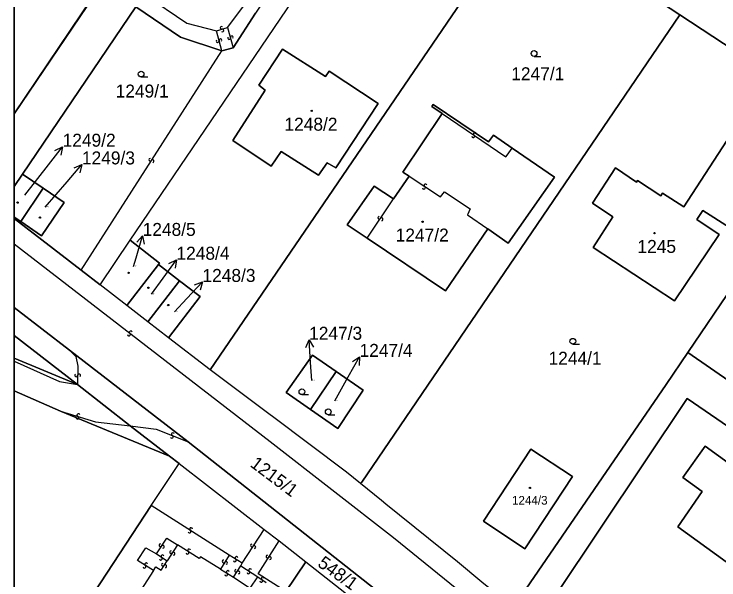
# Model space of a CAD drawing. Extents: x -600309 to -598967, y -1161267 to -1160292.
# Drawn here: x -600308.5 to -600216.2, y -1160403.9 to -1160329.8 of the extents above; entities that cross this region are included whole.
import ezdxf

# ---------------------------------------------------------------- set-up
doc = ezdxf.new("R2010")
doc.units = 0
for name, color, linetype in [('Level 1', 7, 'Continuous'), ('Level 13', 7, 'Continuous'), ('Level 3', 7, 'Continuous'), ('Level 4', 7, 'Continuous'), ('Level 5', 7, 'Continuous'), ('Level 57', 7, 'Continuous'), ('Level 60', 7, 'Continuous'), ('Vrstva 60', 7, 'Continuous'), ('Vrstva 63', 7, 'Continuous')]:
    doc.layers.add(name, color=color, linetype=linetype)

msp = doc.modelspace()

# ---------------------------------------------------------------- linework, layer by layer
at = {"layer": 'Level 1'}
for p, q in [((-600308.541, -1160342.846), (-600296.1, -1160324.42)), ((-600308.541, -1160352.373), (-600307.43, -1160350.76)), ((-600308.541, -1160356.385), (-600307.64, -1160356.98)), ((-600299.76, -1160363.36), (-600308.541, -1160356.593)), ((-600301.3, -1160373.82), (-600308.541, -1160368.236)), ((-600308.541, -1160371.919), (-600300.23, -1160378.34)), ((-600308.541, -1160374.894), (-600300.23, -1160378.34)), ((-600308.541, -1160379.184), (-600302.45, -1160381.81))]:
    msp.add_line(p, q, dxfattribs=at)
for points in [[(-600293.32, -1160359.44), (-600257.23, -1160306.23)], [(-600282.85, -1160376.42), (-600241.86, -1160316.33)], [(-600229.14, -1160324.7), (-600221.27, -1160329.87)], [(-600307.43, -1160350.76), (-600292.59, -1160328.82)], [(-600292.59, -1160328.82), (-600286.75, -1160332.8), (-600281.32, -1160334.59)], [(-600279.81, -1160334.2), (-600276.88, -1160329.68)], [(-600263.15, -1160391.32), (-600262.97, -1160391.13), (-600221.27, -1160329.87)], [(-600221.27, -1160329.87), (-600199.77, -1160343.98)], [(-600281.32, -1160334.59), (-600279.81, -1160334.2)], [(-600273.37, -1160334.39), (-600267.73, -1160337.96), (-600267.24, -1160337.25), (-600260.83, -1160341.49), (-600266.36, -1160349.95), (-600267.49, -1160349.28), (-600268.63, -1160350.88), (-600273.52, -1160347.79), (-600274.86, -1160349.72), (-600279.89, -1160346.36), (-600275.61, -1160339.77), (-600276.46, -1160339.11), (-600273.37, -1160334.39)], [(-600252.44, -1160342.8), (-600253.8, -1160341.89), (-600253.63, -1160341.64), (-600246.36, -1160346.54), (-600245.7, -1160345.67), (-600243.27, -1160347.35)], [(-600256.77, -1160351.05), (-600257.58, -1160350.49), (-600252.44, -1160342.8)], [(-600220.24, -1160374.15), (-600199.77, -1160343.98)], [(-600214.78, -1160357.78), (-600208.56, -1160348.24), (-600214.01, -1160344.68), (-600220.76, -1160355.06), (-600223.56, -1160353.24), (-600223.79, -1160353.59), (-600226.82, -1160351.62), (-600226.94, -1160351.8), (-600229.71, -1160349.95), (-600232.74, -1160354.59), (-600230.04, -1160356.36), (-600232.65, -1160360.4), (-600221.98, -1160367.38), (-600216.14, -1160358.66), (-600219.03, -1160356.71), (-600218.26, -1160355.51), (-600214.78, -1160357.78)], [(-600243.27, -1160347.35), (-600237.72, -1160351.15), (-600243.76, -1160359.82), (-600246.44, -1160357.95)], [(-600304.72, -1160352.6), (-600307.43, -1160350.76)], [(-600258.79, -1160354.01), (-600256.77, -1160351.05)], [(-600307.64, -1160356.98), (-600304.94, -1160358.83), (-600301.97, -1160354.48), (-600304.72, -1160352.6)], [(-600304.72, -1160352.6), (-600307.64, -1160356.98)], [(-600262.24, -1160359.16), (-600264.87, -1160357.4), (-600261.34, -1160352.32), (-600258.79, -1160354.01)], [(-600246.44, -1160357.95), (-600251.99, -1160366.04), (-600262.24, -1160359.16)], [(-600297.28, -1160365.27), (-600293.32, -1160359.44)], [(-600293.32, -1160359.44), (-600289.47, -1160362.42), (-600289.61, -1160362.6)], [(-600293.77, -1160367.98), (-600289.61, -1160362.6)], [(-600289.61, -1160362.6), (-600286.84, -1160364.74)], [(-600297.28, -1160365.27), (-600299.76, -1160363.36)], [(-600286.84, -1160364.74), (-600291, -1160370.12)], [(-600286.84, -1160364.74), (-600284.15, -1160366.82), (-600288.31, -1160372.2)], [(-600293.77, -1160367.98), (-600297.28, -1160365.27)], [(-600029.82, -1160579.77), (-600047.03, -1160569.17), (-600070.48, -1160554.56), (-600111.58, -1160529.03), (-600126.1, -1160520.21), (-600138.76, -1160511.76), (-600151.84, -1160502.25), (-600159.7, -1160496.34), (-600170.75, -1160487.14), (-600176.1, -1160482.15), (-600185.22, -1160473.25), (-600206.08, -1160453.49), (-600217.54, -1160442.6), (-600229.41, -1160431.52), (-600247.87, -1160415.66), (-600254.33, -1160410.63), (-600285.71, -1160385.84), (-600301.3, -1160373.82), (-600308.541, -1160368.236)], [(-600291, -1160370.12), (-600293.77, -1160367.98)], [(-600288.31, -1160372.2), (-600291, -1160370.12)], [(-600282.85, -1160376.42), (-600288.31, -1160372.2)], [(-600285.71, -1160385.84), (-600301.3, -1160373.82)], [(-600266.32, -1160376.62), (-600269.42, -1160374.51), (-600272.89, -1160379.38), (-600269.71, -1160381.61)], [(-600243.16, -1160407.61), (-600242.98, -1160407.4), (-600223.07, -1160378.32), (-600220.24, -1160374.15)], [(-600220.24, -1160374.15), (-600205.39, -1160384.4)], [(-600263.15, -1160391.32), (-600264.98, -1160389.81), (-600274.67, -1160382.53), (-600274.96, -1160382.3), (-600282.85, -1160376.42)], [(-600266.32, -1160376.62), (-600269.71, -1160381.61)], [(-600266.32, -1160376.62), (-600262.78, -1160379.08), (-600266.12, -1160384.1), (-600269.71, -1160381.61)], [(-600293.32, -1160383.74), (-600300.23, -1160378.34)], [(-600235.83, -1160413.97), (-600237.42, -1160405.71), (-600220.3, -1160380.18), (-600204.05, -1160391.32), (-600193.72, -1160398.49)], [(-600302.45, -1160381.81), (-600288.16, -1160387.74)], [(-600288.16, -1160387.74), (-600293.32, -1160383.74)], [(-600000.45, -1160595.4), (-600016.14, -1160587.57), (-600029.82, -1160579.77), (-600047.03, -1160569.17), (-600070.48, -1160554.56), (-600111.58, -1160529.03), (-600126.1, -1160520.21), (-600138.76, -1160511.76), (-600151.84, -1160502.25), (-600159.7, -1160496.34), (-600170.75, -1160487.14), (-600176.1, -1160482.15), (-600185.22, -1160473.25), (-600206.08, -1160453.49), (-600217.54, -1160442.6), (-600229.41, -1160431.52), (-600247.87, -1160415.66), (-600254.33, -1160410.63), (-600285.71, -1160385.84)], [(-600241.6, -1160399.85), (-600247.03, -1160396.26), (-600240.79, -1160386.82), (-600235.36, -1160390.41), (-600241.6, -1160399.85)], [(-600212.69, -1160403.4), (-600221.56, -1160396.97), (-600218.35, -1160392.37), (-600220.87, -1160390.5), (-600217.96, -1160386.41), (-600206.49, -1160394.71), (-600212.69, -1160403.4)], [(-600288.16, -1160387.74), (-600286.91, -1160388.7)], [(-600290.57, -1160394.2), (-600286.91, -1160388.7)], [(-600286.91, -1160388.7), (-600275.76, -1160397.32)], [(-600243.16, -1160407.61), (-600244.73, -1160406.23), (-600247.25, -1160404.22), (-600250.43, -1160401.59), (-600259.8, -1160394.03), (-600260.37, -1160393.54), (-600263.15, -1160391.32)], [(-600290.57, -1160394.2), (-600298.04, -1160405.59)], [(-600275.76, -1160397.32), (-600273.8, -1160398.84)], [(-600273.8, -1160398.84), (-600270.28, -1160401.56)], [(-600272.94, -1160405.48), (-600270.28, -1160401.56)], [(-600270.28, -1160401.56), (-600257.21, -1160411.88)]]:
    msp.add_lwpolyline(points, dxfattribs=at)
at = {"layer": 'Level 13'}
for centre, start, end in [((-600281.336, -1160331.592), 52.49674, 284.59474), ((-600281.243, -1160331.948), 232.28229, 104.87229), ((-600281.858, -1160333.327), 142.53529, 14.63329), ((-600281.502, -1160333.233), 322.32084, 194.91084), ((-600280.357, -1160332.929), 142.87323, 15.46323), ((-600280.002, -1160332.832), 323.08768, 195.18568), ((-600248.155, -1160345.489), 3.10076, 235.19876), ((-600248.364, -1160345.792), 182.88631, 55.47631), ((-600290.694, -1160348.879), 94.71508, 326.81308), ((-600290.385, -1160349.08), 274.50062, 147.09062), ((-600254.811, -1160352.554), 184.0808, 56.6708), ((-600254.608, -1160352.246), 4.29526, 236.39326), ((-600260.672, -1160356.476), 93.55449, 325.65249), ((-600260.368, -1160356.683), 273.34003, 145.93003), ((-600293.257, -1160371.495), 359.4942, 232.0842), ((-600293.484, -1160371.785), 179.70865, 51.80665), ((-600300.394, -1160377.135), 125.96479, 358.55479), ((-600300.026, -1160377.146), 306.17924, 178.27724), ((-600300.114, -1160382.344), 20.19058, 252.28857), ((-600300.225, -1160382.696), 199.97612, 72.56612), ((-600287.868, -1160385.191), 195.66402, 68.25402), ((-600287.731, -1160384.849), 15.87847, 247.97647), ((-600285.351, -1160397.295), 4.7523, 237.3423), ((-600285.55, -1160397.605), 184.96676, 57.06475), ((-600289.353, -1160399.397), 93.87472, 325.97271), ((-600289.047, -1160399.602), 273.66026, 146.25026), ((-600285.61, -1160400.075), 4.60827, 237.19828), ((-600277.363, -1160399.438), 94.22204, 326.32004), ((-600277.056, -1160399.641), 274.00759, 146.59759), ((-600289.086, -1160400.848), 3.58765, 235.68564), ((-600287.954, -1160400.3), 94.40946, 326.99946), ((-600287.646, -1160400.501), 274.62391, 146.72191), ((-600285.811, -1160400.385), 184.82273, 56.92073), ((-600279.401, -1160401.075), 4.75373, 237.34373), ((-600275.325, -1160400.889), 94.80658, 326.90458), ((-600275.015, -1160401.09), 274.59213, 147.18213), ((-600291.242, -1160401.904), 5.07903, 237.66903), ((-600289.293, -1160401.153), 183.37319, 55.96319), ((-600289.034, -1160401.959), 94.56577, 326.66376), ((-600281.065, -1160401.51), 94.64636, 327.23636), ((-600280.755, -1160401.711), 274.86082, 146.95882), ((-600279.6, -1160401.385), 184.96819, 57.06619), ((-600291.439, -1160402.215), 185.29348, 57.39148), ((-600288.726, -1160402.16), 274.35131, 146.94131), ((-600280.53, -1160402.905), 5.24774, 237.34573), ((-600279.445, -1160402.75), 94.9261, 327.0241), ((-600279.135, -1160402.949), 274.71164, 147.30164), ((-600277.608, -1160402.656), 4.28512, 236.38312), ((-600280.729, -1160403.215), 185.03328, 57.62328), ((-600277.811, -1160402.964), 184.07067, 56.66067), ((-600275.934, -1160403.759), 2.97389, 235.07189), ((-600276.145, -1160404.061), 182.75943, 55.34943)]:
    msp.add_arc(centre, 0.184, start, end, dxfattribs=at)
at = {"layer": 'Level 3'}
for points in [[(-600280.55, -1160331.57), (-600273.58, -1160322.21)], [(-600291.44, -1160327.18), (-600285.89, -1160330.98), (-600282.03, -1160331.97)], [(-600282.03, -1160331.97), (-600280.55, -1160331.57)], [(-600280.55, -1160331.57), (-600279.81, -1160334.2)], [(-600281.32, -1160334.59), (-600282.03, -1160331.97)], [(-600299.76, -1160363.36), (-600281.32, -1160334.59)], [(-600252.44, -1160342.8), (-600244.09, -1160348.49), (-600243.91, -1160348.28), (-600243.27, -1160347.35)], [(-600256.77, -1160351.05), (-600252.64, -1160353.74), (-600252.14, -1160353.08), (-600248.75, -1160355.33), (-600249.12, -1160356.09), (-600246.44, -1160357.95)], [(-600262.24, -1160359.16), (-600258.79, -1160354.01)], [(-600125.19, -1160509.33), (-600126.01, -1160509.76), (-600127.13, -1160510.07), (-600127.94, -1160510.13), (-600128.79, -1160510.07), (-600129.93, -1160509.77), (-600130.99, -1160509.15), (-600139.71, -1160503.93), (-600147.26, -1160498.02), (-600154.8, -1160492.15), (-600161.97, -1160486.6), (-600165.04, -1160483.54), (-600170.09, -1160478.96), (-600176.09, -1160473.27), (-600190.99, -1160459.57), (-600204.18, -1160445.56), (-600212.67, -1160438.18), (-600221.71, -1160429.76), (-600228.39, -1160423.74), (-600246.35, -1160408.54), (-600258.81, -1160398.41), (-600274.98, -1160385.83), (-600308.541, -1160359.925)], [(-600301.3, -1160373.82), (-600300.46, -1160374.67), (-600300.18, -1160375.94), (-600300.23, -1160378.34)], [(-600308.541, -1160375.276), (-600302.59, -1160377.95), (-600300.23, -1160378.34)], [(-600302.45, -1160381.81), (-600297.89, -1160383.22), (-600293.32, -1160383.74)], [(-600293.32, -1160383.74), (-600289.9, -1160384.19), (-600285.71, -1160385.84)], [(-600280.33, -1160400.7), (-600290.57, -1160394.2)], [(-600278.66, -1160401.76), (-600275.76, -1160397.32)], [(-600289.88, -1160400.53), (-600288.51, -1160398.46), (-600287.12, -1160399.33)], [(-600272.94, -1160405.48), (-600276.54, -1160403.13), (-600273.8, -1160398.84)], [(-600290.29, -1160402.71), (-600292.38, -1160401.4), (-600291.28, -1160399.73), (-600289.88, -1160400.53)], [(-600287.12, -1160399.33), (-600288.49, -1160401.46)], [(-600281.49, -1160402.52), (-600284.11, -1160400.92), (-600284.3, -1160401.13), (-600287.12, -1160399.33)], [(-600289.88, -1160400.53), (-600288.49, -1160401.46)], [(-600280.33, -1160400.7), (-600281.49, -1160402.52)], [(-600278.66, -1160401.76), (-600280.33, -1160400.7)], [(-600290.29, -1160402.71), (-600289.96, -1160402.23), (-600289.27, -1160402.67), (-600288.49, -1160401.46)], [(-600278.81, -1160402.09), (-600278.66, -1160401.76)], [(-600290.29, -1160402.71), (-600293.12, -1160407.11)], [(-600281.49, -1160402.52), (-600279.77, -1160403.6)], [(-600279.77, -1160403.6), (-600278.81, -1160402.09)], [(-600278.81, -1160402.09), (-600276.6, -1160403.53)], [(-600279.77, -1160403.6), (-600277.59, -1160405.01)], [(-600277.59, -1160405.01), (-600276.6, -1160403.53)], [(-600276.6, -1160403.53), (-600275.49, -1160404.29)]]:
    msp.add_lwpolyline(points, dxfattribs=at)
at = {"layer": 'Level 5'}
for p, q in [((-600240.38, -1160335.33), (-600239.505, -1160335.33)), ((-600291.89, -1160338.03), (-600291.015, -1160338.03)), ((-600235.3, -1160373.04), (-600234.425, -1160373.04)), ((-600270.81, -1160379.66), (-600269.935, -1160379.66)), ((-600267.36, -1160382.29), (-600266.485, -1160382.29))]:
    msp.add_line(p, q, dxfattribs=at)
for centre, radius in [((-600240.38, -1160334.955), 0.375), ((-600291.89, -1160337.655), 0.375), ((-600269.52, -1160342.47), 0.09), ((-600269.52, -1160342.47), 0.0521), ((-600308.08, -1160354.49), 0.09), ((-600308.08, -1160354.49), 0.0521), ((-600305.15, -1160356.46), 0.09), ((-600305.15, -1160356.46), 0.0521), ((-600255, -1160357), 0.09), ((-600255, -1160357), 0.0521), ((-600224.6, -1160358.49), 0.09), ((-600224.6, -1160358.49), 0.0521), ((-600293.53, -1160363.7), 0.09), ((-600293.53, -1160363.7), 0.0521), ((-600290.93, -1160365.66), 0.09), ((-600290.93, -1160365.66), 0.0521), ((-600288.33, -1160367.93), 0.09), ((-600288.33, -1160367.93), 0.0521), ((-600235.3, -1160372.665), 0.375), ((-600270.81, -1160379.285), 0.375), ((-600267.36, -1160381.915), 0.375), ((-600240.93, -1160391.88), 0.09), ((-600240.93, -1160391.88), 0.0521)]:
    msp.add_circle(centre, radius, dxfattribs=at)
at = {"layer": 'Level 57'}
for p, q in [((-600304.021, -1160349.539), (-600302.18, -1160347.17)), ((-600307.13, -1160353.54), (-600304.021, -1160349.539)), ((-600301.6, -1160351.769), (-600299.65, -1160349.49)), ((-600304.45, -1160355.1), (-600301.6, -1160351.769)), ((-600292.541, -1160361.737), (-600291.69, -1160358.86)), ((-600292.87, -1160362.85), (-600292.541, -1160361.737)), ((-600289.015, -1160364.413), (-600287.26, -1160361.98)), ((-600290.52, -1160366.5), (-600289.015, -1160364.413)), ((-600285.9, -1160367.08), (-600283.85, -1160364.89)), ((-600287.52, -1160368.81), (-600285.9, -1160367.08)), ((-600269.674, -1160375.464), (-600269.87, -1160372.47)), ((-600264.74, -1160377.32), (-600263.26, -1160374.71)), ((-600269.52, -1160377.81), (-600269.674, -1160375.464)), ((-600266.52, -1160380.46), (-600264.74, -1160377.32))]:
    msp.add_line(p, q, dxfattribs=at)
for points in [[(-600303.189, -1160347.653), (-600302.18, -1160347.17), (-600302.399, -1160348.267)], [(-600300.68, -1160349.924), (-600299.65, -1160349.49), (-600299.92, -1160350.574)], [(-600292.453, -1160359.677), (-600291.69, -1160358.86), (-600291.494, -1160359.961)], [(-600288.251, -1160362.498), (-600287.26, -1160361.98), (-600287.44, -1160363.083)], [(-600284.898, -1160365.278), (-600283.85, -1160364.89), (-600284.168, -1160365.962)], [(-600270.304, -1160373.501), (-600269.87, -1160372.47), (-600269.306, -1160373.436)], [(-600264.189, -1160375.334), (-600263.26, -1160374.71), (-600263.319, -1160375.827)]]:
    msp.add_lwpolyline(points, dxfattribs=at)
at = {"layer": 'Level 60'}
msp.add_lwpolyline([(-600199.77, -1160343.98), (-600221.27, -1160329.87), (-600229.14, -1160324.7), (-600216.43, -1160305.71), (-600215.1, -1160306.58)], dxfattribs=at)
for points in [[(-600241.86, -1160316.33), (-600282.85, -1160376.42), (-600288.31, -1160372.2), (-600284.15, -1160366.82), (-600286.84, -1160364.74), (-600289.61, -1160362.6), (-600289.47, -1160362.42), (-600293.32, -1160359.44), (-600257.23, -1160306.23), (-600242.97, -1160315.51)], [(-600286.75, -1160332.8), (-600292.59, -1160328.82), (-600291.44, -1160327.18), (-600289, -1160323.54), (-600281.11, -1160311.9), (-600279.44, -1160309.47), (-600278.78, -1160308.52), (-600271.58, -1160313.38), (-600272.07, -1160314.13), (-600271.42, -1160314.57), (-600270.55, -1160315.2), (-600269.04, -1160316.19), (-600266.59, -1160312.66), (-600263.88, -1160314.52), (-600266.32, -1160318.03), (-600268.21, -1160316.83), (-600272.38, -1160322.95), (-600276.88, -1160329.68), (-600279.81, -1160334.2), (-600281.32, -1160334.59)], [(-600262.97, -1160391.13), (-600263.15, -1160391.32), (-600264.98, -1160389.81), (-600274.67, -1160382.53), (-600274.96, -1160382.3), (-600282.85, -1160376.42), (-600241.86, -1160316.33), (-600229.14, -1160324.7), (-600221.27, -1160329.87)], [(-600243.16, -1160407.61), (-600244.73, -1160406.23), (-600247.25, -1160404.22), (-600250.43, -1160401.59), (-600259.8, -1160394.03), (-600260.37, -1160393.54), (-600263.15, -1160391.32), (-600262.97, -1160391.13), (-600221.27, -1160329.87), (-600199.77, -1160343.98), (-600220.24, -1160374.15), (-600223.07, -1160378.32), (-600242.98, -1160407.4)], [(-600273.37, -1160334.39), (-600267.73, -1160337.96), (-600267.24, -1160337.25), (-600260.83, -1160341.49), (-600266.36, -1160349.95), (-600267.49, -1160349.28), (-600268.63, -1160350.88), (-600273.52, -1160347.79), (-600274.86, -1160349.72), (-600279.89, -1160346.36), (-600275.61, -1160339.77), (-600276.46, -1160339.11)], [(-600267.73, -1160337.96), (-600273.37, -1160334.39), (-600276.46, -1160339.11), (-600275.61, -1160339.77), (-600279.89, -1160346.36), (-600274.86, -1160349.72), (-600273.52, -1160347.79), (-600268.63, -1160350.88), (-600267.49, -1160349.28), (-600266.36, -1160349.95), (-600260.83, -1160341.49), (-600267.24, -1160337.25)], [(-600237.72, -1160351.15), (-600243.76, -1160359.82), (-600246.44, -1160357.95), (-600251.99, -1160366.04), (-600262.24, -1160359.16), (-600264.87, -1160357.4), (-600261.34, -1160352.32), (-600258.79, -1160354.01), (-600256.77, -1160351.05), (-600257.58, -1160350.49), (-600252.44, -1160342.8), (-600253.8, -1160341.89), (-600253.63, -1160341.64), (-600246.36, -1160346.54), (-600245.7, -1160345.67), (-600243.27, -1160347.35)], [(-600243.76, -1160359.82), (-600237.72, -1160351.15), (-600243.27, -1160347.35), (-600245.7, -1160345.67), (-600246.36, -1160346.54), (-600253.63, -1160341.64), (-600253.8, -1160341.89), (-600252.44, -1160342.8), (-600257.58, -1160350.49), (-600256.77, -1160351.05), (-600258.79, -1160354.01), (-600261.34, -1160352.32), (-600264.87, -1160357.4), (-600262.24, -1160359.16), (-600251.99, -1160366.04), (-600246.44, -1160357.95)], [(-600220.24, -1160374.15), (-600199.77, -1160343.98), (-600184.93, -1160353.79), (-600185.89, -1160355.37), (-600197.45, -1160347.61), (-600203.6, -1160356.82), (-600192.04, -1160364.57), (-600199.44, -1160375.52), (-600205.39, -1160384.4)], [(-600208.56, -1160348.24), (-600214.78, -1160357.78), (-600218.26, -1160355.51), (-600219.03, -1160356.71), (-600216.14, -1160358.66), (-600221.98, -1160367.38), (-600232.65, -1160360.4), (-600230.04, -1160356.36), (-600232.74, -1160354.59), (-600229.71, -1160349.95), (-600226.94, -1160351.8), (-600226.82, -1160351.62), (-600223.79, -1160353.59), (-600223.56, -1160353.24), (-600220.76, -1160355.06), (-600214.01, -1160344.68)], [(-600214.78, -1160357.78), (-600208.56, -1160348.24), (-600214.01, -1160344.68), (-600220.76, -1160355.06), (-600223.56, -1160353.24), (-600223.79, -1160353.59), (-600226.82, -1160351.62), (-600226.94, -1160351.8), (-600229.71, -1160349.95), (-600232.74, -1160354.59), (-600230.04, -1160356.36), (-600232.65, -1160360.4), (-600221.98, -1160367.38), (-600216.14, -1160358.66), (-600219.03, -1160356.71), (-600218.26, -1160355.51)], [(-600304.94, -1160358.83), (-600307.64, -1160356.98), (-600304.72, -1160352.6), (-600301.97, -1160354.48)], [(-600289.61, -1160362.6), (-600293.77, -1160367.98), (-600297.28, -1160365.27), (-600293.32, -1160359.44), (-600289.47, -1160362.42)], [(-600291, -1160370.12), (-600293.77, -1160367.98), (-600289.61, -1160362.6), (-600286.84, -1160364.74)], [(-600288.31, -1160372.2), (-600291, -1160370.12), (-600286.84, -1160364.74), (-600284.15, -1160366.82)], [(-600266.32, -1160376.62), (-600269.42, -1160374.51), (-600272.89, -1160379.38), (-600269.71, -1160381.61), (-600266.12, -1160384.1), (-600262.78, -1160379.08)], [(-600269.42, -1160374.51), (-600266.32, -1160376.62), (-600269.71, -1160381.61), (-600272.89, -1160379.38)], [(-600243.16, -1160407.61), (-600242.98, -1160407.4), (-600223.07, -1160378.32), (-600220.24, -1160374.15), (-600205.39, -1160384.4), (-600190.91, -1160394.34), (-600193.72, -1160398.49), (-600204.05, -1160391.32), (-600220.3, -1160380.18), (-600237.42, -1160405.71), (-600235.83, -1160413.97)], [(-600269.71, -1160381.61), (-600266.32, -1160376.62), (-600262.78, -1160379.08), (-600266.12, -1160384.1)], [(-600215.73, -1160431), (-600215.99, -1160431.39), (-600235.83, -1160413.97), (-600237.42, -1160405.71), (-600220.3, -1160380.18), (-600204.05, -1160391.32), (-600193.72, -1160398.49)], [(-600241.6, -1160399.85), (-600247.03, -1160396.26), (-600240.79, -1160386.82), (-600235.36, -1160390.41)], [(-600247.03, -1160396.26), (-600241.6, -1160399.85), (-600235.36, -1160390.41), (-600240.79, -1160386.82)], [(-600212.69, -1160403.4), (-600221.56, -1160396.97), (-600218.35, -1160392.37), (-600220.87, -1160390.5), (-600217.96, -1160386.41), (-600206.49, -1160394.71)], [(-600221.56, -1160396.97), (-600212.69, -1160403.4), (-600206.49, -1160394.71), (-600217.96, -1160386.41), (-600220.87, -1160390.5), (-600218.35, -1160392.37)], [(-600298.04, -1160405.59), (-600290.57, -1160394.2), (-600286.91, -1160388.7), (-600275.76, -1160397.32), (-600273.8, -1160398.84), (-600270.28, -1160401.56), (-600272.94, -1160405.48), (-600273.13, -1160405.78), (-600276.37, -1160410.54), (-600281.95, -1160418.77), (-600295.24, -1160410.43), (-600293.8, -1160408.16), (-600294.73, -1160407.57), (-600295.33, -1160407.28), (-600297.74, -1160411.1), (-600300.52, -1160409.37)], [(-600270.28, -1160401.56), (-600257.21, -1160411.88), (-600258.61, -1160413.81), (-600259.57, -1160415.09), (-600260.17, -1160415.87), (-600267.84, -1160426.04), (-600268.54, -1160427.01), (-600269.59, -1160428.35), (-600271.65, -1160431.13), (-600284.59, -1160422.62), (-600281.95, -1160418.77), (-600276.37, -1160410.54), (-600273.13, -1160405.78), (-600272.94, -1160405.48)]]:
    msp.add_lwpolyline(points, close=True, dxfattribs=at)
at = {"layer": 'Vrstva 60'}
for points in [[(-600308.541, -1160320.794), (-600308.541, -1160342.846), (-600296.1, -1160324.42), (-600306, -1160319.03), (-600294.41, -1160302.17), (-600288.87, -1160305.93), (-600287.64, -1160304.09), (-600279.44, -1160309.47), (-600278.78, -1160308.52), (-600270.99, -1160297.05), (-600278.146, -1160292.347), (-600289.118, -1160292.347)], [(-600308.541, -1160342.846), (-600308.541, -1160352.373), (-600307.43, -1160350.76), (-600292.59, -1160328.82), (-600291.44, -1160327.18), (-600289, -1160323.54), (-600281.11, -1160311.9), (-600279.44, -1160309.47), (-600287.64, -1160304.09), (-600288.87, -1160305.93), (-600294.41, -1160302.17), (-600306, -1160319.03), (-600296.1, -1160324.42)], [(-600308.541, -1160352.373), (-600308.541, -1160356.385), (-600307.64, -1160356.98), (-600304.72, -1160352.6), (-600307.43, -1160350.76)], [(-600308.541, -1160371.919), (-600308.541, -1160374.894), (-600300.23, -1160378.34)], [(-600308.541, -1160374.894), (-600308.541, -1160379.184), (-600302.45, -1160381.81), (-600288.16, -1160387.74), (-600293.32, -1160383.74), (-600300.23, -1160378.34)], [(-600308.541, -1160379.184), (-600308.541, -1160418.779), (-600307.25, -1160419.63), (-600300.52, -1160409.37), (-600298.04, -1160405.59), (-600290.57, -1160394.2), (-600286.91, -1160388.7), (-600288.16, -1160387.74), (-600302.45, -1160381.81)]]:
    msp.add_lwpolyline(points, close=True, dxfattribs=at)
for points in [[(-600276.88, -1160329.68), (-600279.81, -1160334.2), (-600281.32, -1160334.59), (-600286.75, -1160332.8), (-600292.59, -1160328.82), (-600307.43, -1160350.76), (-600304.72, -1160352.6), (-600301.97, -1160354.48), (-600304.94, -1160358.83), (-600307.64, -1160356.98), (-600308.541, -1160356.385), (-600308.541, -1160356.593), (-600299.76, -1160363.36), (-600297.28, -1160365.27), (-600293.32, -1160359.44), (-600257.23, -1160306.23)], [(-600247.25, -1160404.22), (-600250.43, -1160401.59), (-600259.8, -1160394.03), (-600260.37, -1160393.54), (-600263.15, -1160391.32), (-600264.98, -1160389.81), (-600274.67, -1160382.53), (-600274.96, -1160382.3), (-600282.85, -1160376.42), (-600288.31, -1160372.2), (-600291, -1160370.12), (-600293.77, -1160367.98), (-600297.28, -1160365.27), (-600299.76, -1160363.36), (-600308.541, -1160356.593), (-600308.541, -1160368.236), (-600301.3, -1160373.82), (-600285.71, -1160385.84), (-600254.33, -1160410.63)], [(-600254.33, -1160410.63), (-600285.71, -1160385.84), (-600301.3, -1160373.82), (-600308.541, -1160368.236), (-600308.541, -1160371.919), (-600300.23, -1160378.34), (-600293.32, -1160383.74), (-600288.16, -1160387.74), (-600286.91, -1160388.7), (-600275.76, -1160397.32), (-600273.8, -1160398.84), (-600270.28, -1160401.56), (-600257.21, -1160411.88)]]:
    msp.add_lwpolyline(points, dxfattribs=at)
at = {"layer": 'Vrstva 63'}
msp.add_lwpolyline([(-600308.541, -1160292.347), (-598967.108, -1160292.347), (-598967.108, -1161267.031), (-600308.541, -1161267.031)], close=True, dxfattribs=at)

# ---------------------------------------------------------------- texts
at = {"layer": 'Level 4'}
for s, height, p in [('1247/1', 1.7, (-600243.373, -1160338.46)), ('1249/1', 1.7, (-600295.228, -1160340.73)), ('1248/2', 1.7, (-600273.104, -1160345.07)), ('1249/2', 0.1, (-600307.13, -1160353.54)), ('1249/3', 0.1, (-600304.45, -1160355.1)), ('1247/2', 1.7, (-600258.525, -1160359.6)), ('1245', 1.7, (-600226.832, -1160361.09)), ('1248/5', 0.1, (-600292.87, -1160362.85)), ('1248/4', 0.1, (-600290.52, -1160366.5)), ('1248/3', 0.1, (-600287.52, -1160368.81)), ('1244/1', 1.7, (-600238.488, -1160375.74)), ('1247/3', 0.1, (-600269.52, -1160377.81)), ('1247/4', 0.1, (-600266.52, -1160380.46)), ('1244/3', 1.14, (-600243.28, -1160394.08))]:
    msp.add_text(s, height=height, dxfattribs=at).set_placement(p)
msp.add_text('548/1', height=1.7, rotation=324, dxfattribs=at).set_placement((-600268.88, -1160402.05))
at = {"layer": 'Level 57'}
for s, p in [('1249/2', (-600302.18, -1160347.17)), ('1249/3', (-600299.65, -1160349.49)), ('1248/5', (-600291.69, -1160358.86)), ('1248/4', (-600287.26, -1160361.98)), ('1248/3', (-600283.85, -1160364.89)), ('1247/3', (-600269.87, -1160372.47)), ('1247/4', (-600263.26, -1160374.71))]:
    msp.add_text(s, height=1.7, dxfattribs=at).set_placement(p)
msp.add_text('1215/1', height=1.7, rotation=323.1, dxfattribs=at).set_placement((-600277.72, -1160388.99))

doc.saveas('drawing.dxf')
